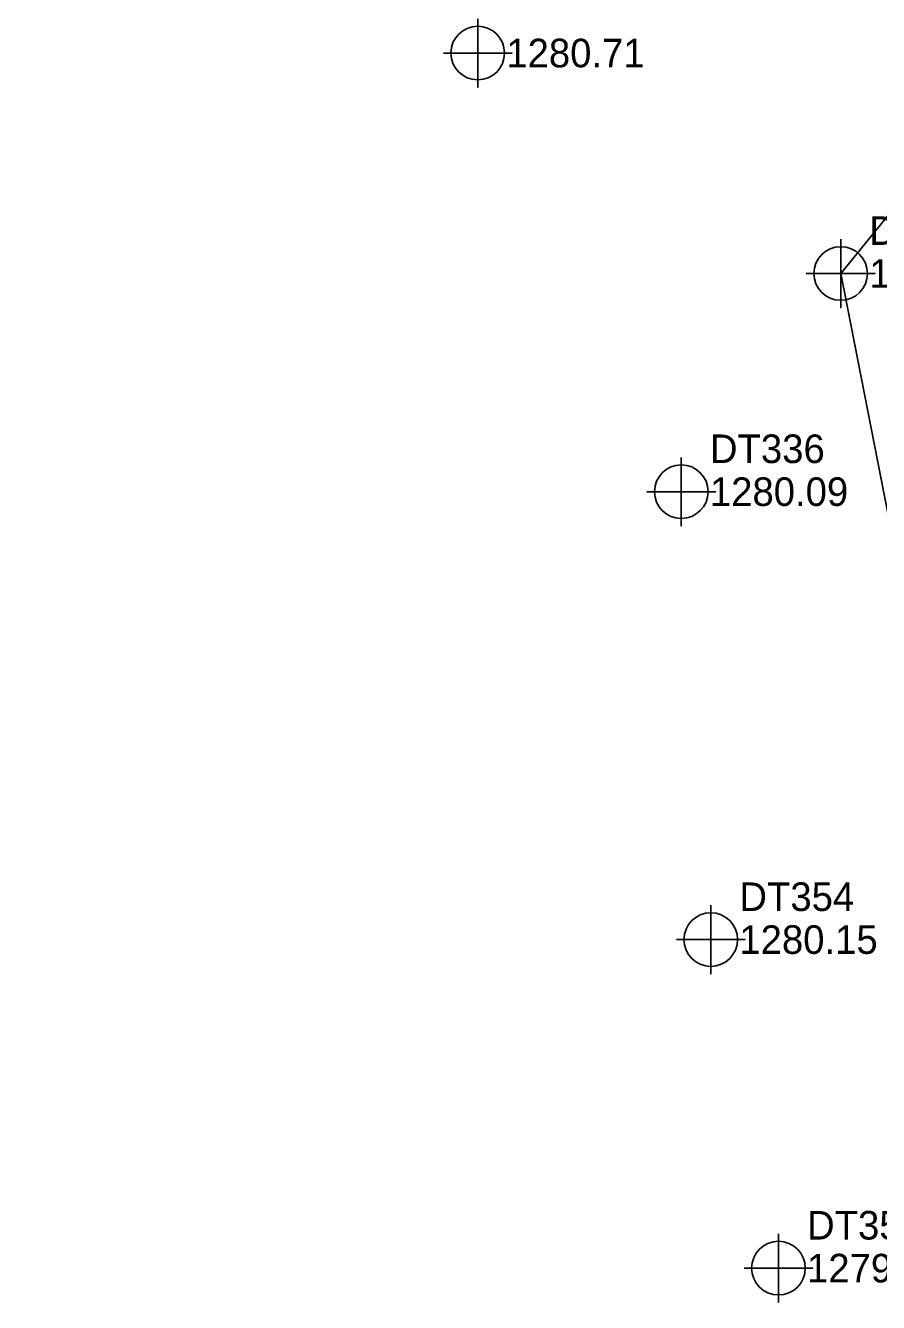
# Model space of a CAD drawing. Extents: x 1394009 to 1394411, y 957864 to 958364.
# Drawn here: x 1394065.4 to 1394139.9, y 958003.1 to 958114.8 of the extents above; entities that cross this region are included whole.
import ezdxf

# ---------------------------------------------------------------- set-up
doc = ezdxf.new("R2010")
doc.units = 0
for name, color, linetype in [('Exist DTM Breakline', 7, 'Continuous'), ('Exist DTM Breakline Cogo Elevation', 7, 'Continuous'), ('Exist DTM Breakline Cogo Number', 7, 'Continuous'), ('Exist DTM Breakline Cogo Point CELL', 7, 'Continuous'), ('Exist DTM Regular Point Cogo Elevation', 7, 'Continuous'), ('PH Exist DTM NCFMP LIDAR Elevation Point', 7, 'Continuous'), ('Raster_Level_0', 7, 'Continuous')]:
    doc.layers.add(name, color=color, linetype=linetype)

msp = doc.modelspace()

# ---------------------------------------------------------------- linework, layer by layer
at = {"layer": 'Exist DTM Breakline'}
msp.add_lwpolyline([(1394065.3665, 958259.7005), (1394076.2432, 958241.6096), (1394098.862, 958196.9887), (1394119.1062, 958160.1529), (1394140.102, 958128.983), (1394150.6899, 958110.4316), (1394136.5853, 958093.0812), (1394143.0953, 958059.9522)], dxfattribs=at)
at = {"layer": 'Exist DTM Breakline Cogo Point CELL'}
msp.add_lwpolyline([(1394136.5853, 958096.0812), (1394136.5853, 958090.0812), (1394136.5853, 958093.0812), (1394139.5853, 958093.0812), (1394133.5853, 958093.0812)], dxfattribs=at)
msp.add_circle((1394136.5853, 958093.0812), 2.344, dxfattribs=at)
at = {"layer": 'PH Exist DTM NCFMP LIDAR Elevation Point'}
for points in [[(1394104.8722, 958115.3508), (1394104.8722, 958109.3508), (1394104.8722, 958112.3508), (1394107.8722, 958112.3508), (1394101.8722, 958112.3508)], [(1394122.6603, 958077.0126), (1394122.6603, 958071.0126), (1394122.6603, 958074.0126), (1394125.6603, 958074.0126), (1394119.6603, 958074.0126)], [(1394125.234, 958037.8632), (1394125.234, 958031.8632), (1394125.234, 958034.8632), (1394128.234, 958034.8632), (1394122.234, 958034.8632)], [(1394131.1475, 958009.1458), (1394131.1475, 958003.1458), (1394131.1475, 958006.1458), (1394134.1475, 958006.1458), (1394128.1475, 958006.1458)]]:
    msp.add_lwpolyline(points, dxfattribs=at)
for centre in [(1394104.8722, 958112.3508), (1394122.6603, 958074.0126), (1394125.234, 958034.8632), (1394131.1475, 958006.1458)]:
    msp.add_circle(centre, 2.344, dxfattribs=at)

# ---------------------------------------------------------------- texts
at = {"layer": 'Exist DTM Breakline Cogo Elevation'}
msp.add_text('1280.32', height=2.5, dxfattribs=at).set_placement((1394139.0853, 958091.8312))
at = {"layer": 'Exist DTM Breakline Cogo Number'}
msp.add_text('DT332', height=2.5, dxfattribs=at).set_placement((1394139.0853, 958095.5812))
at = {"layer": 'Exist DTM Regular Point Cogo Elevation'}
for s, p in [('1280.71', (1394107.3722, 958111.1008)), ('1280.09', (1394125.1603, 958072.7626)), ('1280.15', (1394127.734, 958033.6132)), ('1279.84', (1394133.6475, 958004.8958))]:
    msp.add_text(s, height=2.5, dxfattribs=at).set_placement(p)
at = {"layer": 'Raster_Level_0'}
for s, p in [('DT336', (1394125.1603, 958076.5126)), ('DT354', (1394127.734, 958037.3632)), ('DT359', (1394133.6475, 958008.6458))]:
    msp.add_text(s, height=2.5, dxfattribs=at).set_placement(p)

doc.saveas('drawing.dxf')
